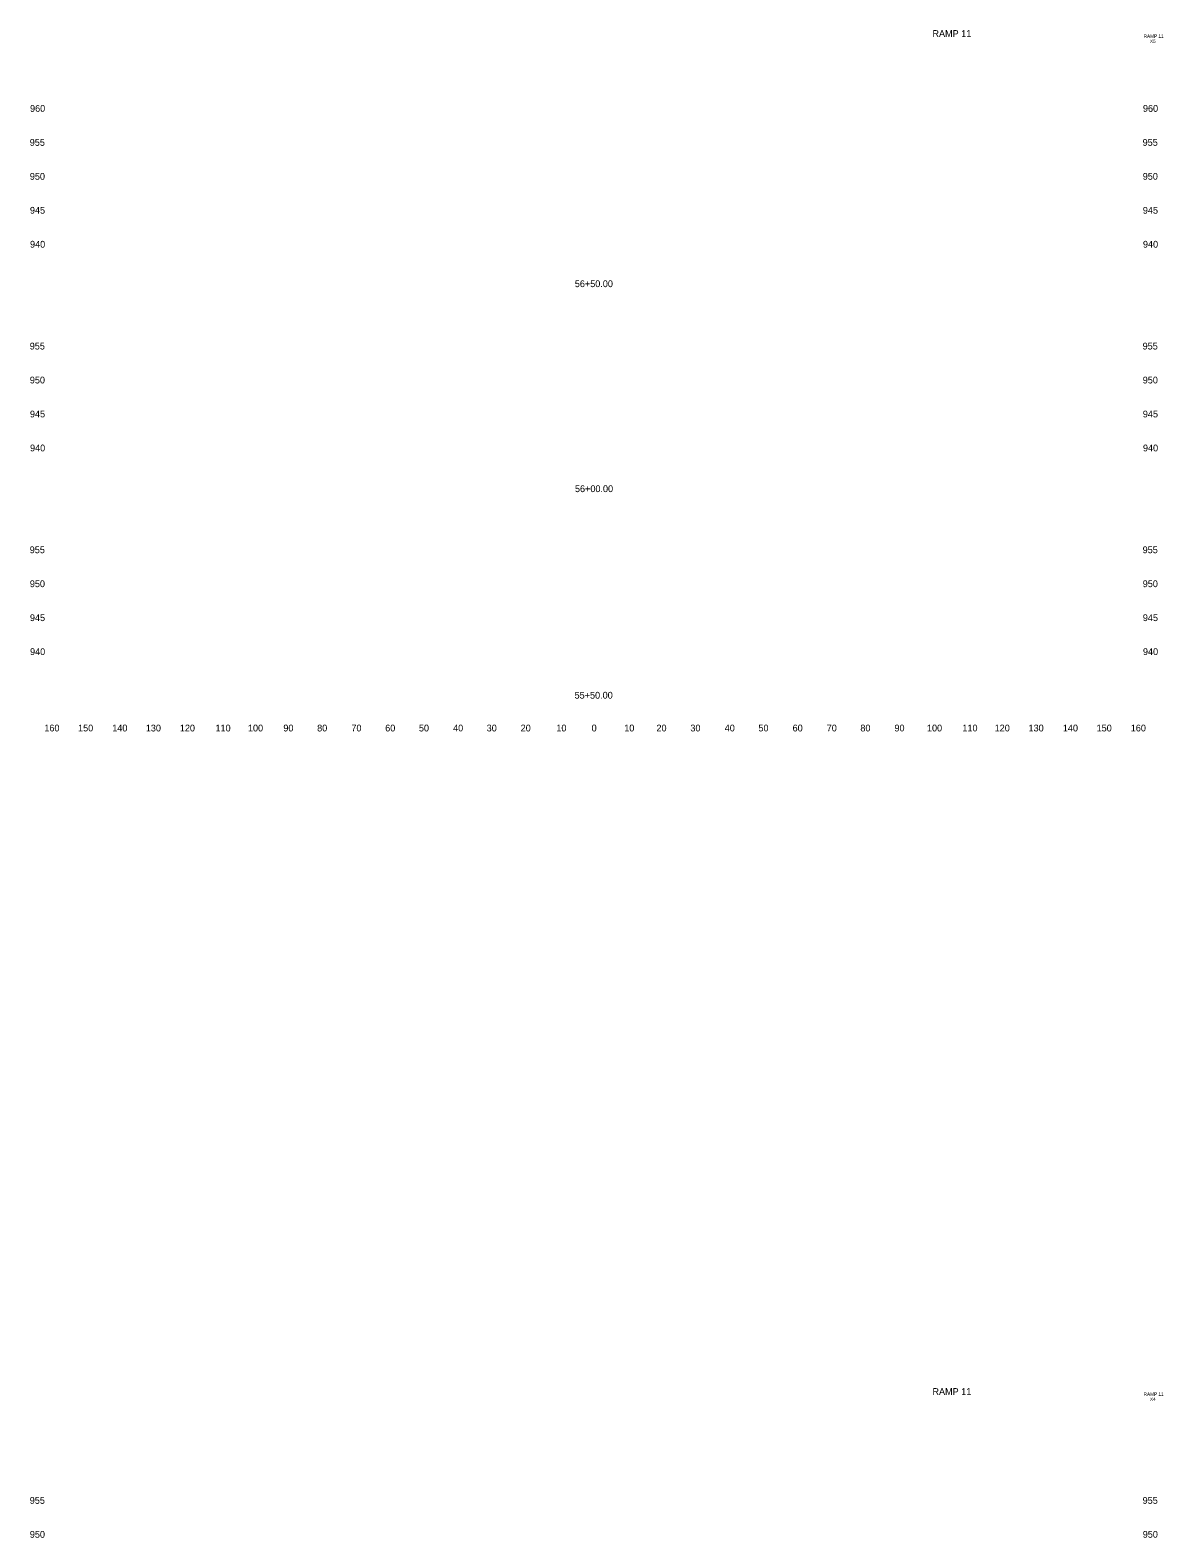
# Model space of a CAD drawing. Extents: x 4994 to 5843, y 4997 to 8804.
# Drawn here: x 4993.9 to 5327.6, y 6360 to 6804.1 of the extents above; entities that cross this region are included whole.
import ezdxf

# ---------------------------------------------------------------- set-up
doc = ezdxf.new("R2010")
doc.units = 0
for name, color, linetype in [('RD_SHT_ID', 7, 'Continuous'), ('RD_XS_TX_Offset', 7, 'Continuous'), ('RD_XS_TX_Station', 7, 'Continuous')]:
    doc.layers.add(name, color=color, linetype=linetype)

msp = doc.modelspace()

# ---------------------------------------------------------------- texts
at = {"layer": 'RD_SHT_ID'}
for s, height, p in [('RAMP 11', 2, (5259.69, 6802.06)), ('RAMP 11', 1, (5321.89, 6801.8)), ('X5', 1, (5323.74, 6800.3)), ('RAMP 11', 2, (5259.69, 6402.06)), ('RAMP 11', 1, (5321.89, 6401.8)), ('X4', 1, (5323.74, 6400.3))]:
    msp.add_text(s, height=height, dxfattribs=at).set_placement(p)
at = {"layer": 'RD_XS_TX_Offset'}
for s, p in [('960', (4993.89, 6780)), ('960', (5321.69, 6780)), ('955', (4993.8, 6770)), ('955', (5321.6, 6770)), ('950', (4993.83, 6760)), ('950', (5321.63, 6760)), ('945', (4993.86, 6750)), ('945', (5321.66, 6750)), ('940', (4993.89, 6740)), ('940', (5321.69, 6740)), ('955', (4993.8, 6710)), ('955', (5321.6, 6710)), ('950', (4993.83, 6700)), ('950', (5321.63, 6700)), ('945', (4993.86, 6690)), ('945', (5321.66, 6690)), ('940', (4993.89, 6680)), ('940', (5321.69, 6680)), ('955', (4993.8, 6650)), ('955', (5321.6, 6650)), ('950', (4993.83, 6640)), ('950', (5321.63, 6640)), ('945', (4993.86, 6630)), ('945', (5321.66, 6630)), ('940', (4993.89, 6620)), ('940', (5321.69, 6620)), ('160', (4998.1, 6597.5)), ('150', (5008.04, 6597.5)), ('140', (5018.1, 6597.5)), ('130', (5027.99, 6597.5)), ('120', (5038.01, 6597.5)), ('110', (5048.51, 6597.5)), ('100', (5058.07, 6597.5)), ('90', (5068.5, 6597.5)), ('80', (5078.46, 6597.5)), ('70', (5088.54, 6597.5)), ('60', (5098.5, 6597.5)), ('50', (5108.43, 6597.5)), ('40', (5118.5, 6597.5)), ('30', (5128.39, 6597.5)), ('20', (5138.4, 6597.5)), ('10', (5148.91, 6597.5)), ('0', (5159.3, 6597.5)), ('0', (5159.3, 6597.5)), ('10', (5168.91, 6597.5)), ('20', (5178.4, 6597.5)), ('30', (5188.39, 6597.5)), ('40', (5198.5, 6597.5)), ('50', (5208.43, 6597.5)), ('60', (5218.5, 6597.5)), ('70', (5228.54, 6597.5)), ('80', (5238.46, 6597.5)), ('90', (5248.5, 6597.5)), ('100', (5258.07, 6597.5)), ('110', (5268.51, 6597.5)), ('120', (5278.01, 6597.5)), ('130', (5287.99, 6597.5)), ('140', (5298.1, 6597.5)), ('150', (5308.04, 6597.5)), ('160', (5318.1, 6597.5)), ('955', (4993.8, 6370)), ('955', (5321.6, 6370)), ('950', (4993.83, 6360)), ('950', (5321.63, 6360))]:
    msp.add_text(s, height=2, dxfattribs=at).set_placement(p)
at = {"layer": 'RD_XS_TX_Station'}
for s, p in [('56+50.00', (5154.35, 6728.37)), ('56+00.00', (5154.39, 6667.99)), ('55+50.00', (5154.29, 6607.16))]:
    msp.add_text(s, height=2, dxfattribs=at).set_placement(p)

doc.saveas('drawing.dxf')
